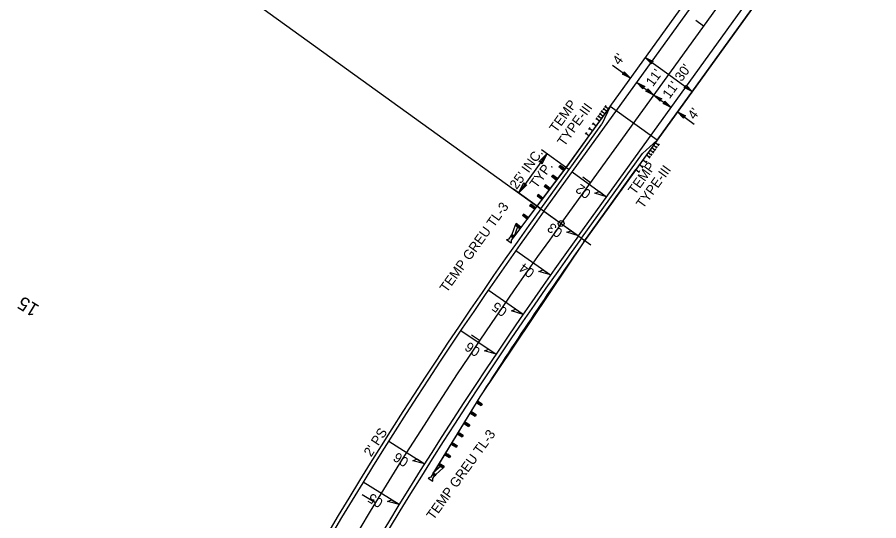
# Model space of a CAD drawing. Extents: x 2189637 to 2190858, y 386969 to 388736.
# Drawn here: x 2189954.9 to 2190401.4, y 387684.2 to 387945.3 of the extents above; entities that cross this region are included whole.
import ezdxf

# ---------------------------------------------------------------- set-up
doc = ezdxf.new("R2010")
doc.units = 0
for name, color, linetype in [('Exist Environmental Wetland Boundary Cogo Number', 7, 'Continuous'), ('Exist Environmental Wetland Boundary Cogo Point CELL', 7, 'Continuous'), ('Exist Horizontal Alignment Tick Label', 7, 'Continuous'), ('Exist Hydro Stream or Body of Water Leader', 7, 'Continuous'), ('Exist Hydro Swamp or Marsh', 7, 'Continuous'), ('Exist Property Corner CELL', 7, 'Continuous'), ('Exist Property Corner Cogo Elevation', 7, 'Continuous'), ('Exist Property Corner Cogo Number', 7, 'Continuous'), ('Exist Property Iron Pin Cogo Elevation', 7, 'Continuous'), ('Exist Property Iron Pin Text', 7, 'Continuous'), ('Exist Roads EOP', 7, 'Continuous'), ('Exist Roads EOT', 7, 'Continuous'), ('Exist Roads Soil', 7, 'Continuous'), ('Exist Structure Major Bridge Seam', 7, 'Continuous'), ('Exist Structure Minor Pipes RCP 18 Inch Cogo Comment', 7, 'Continuous'), ('Exist Structure Minor Pipes RCP 18 Inch Cogo Elevation', 7, 'Continuous'), ('Exist Structure Minor Pipes RCP 18 Inch Leader', 7, 'Continuous'), ('Prop Parcel Number Text', 7, 'Continuous')]:
    doc.layers.add(name, color=color, linetype=linetype)

msp = doc.modelspace()

# ---------------------------------------------------------------- linework, layer by layer
at = {"layer": 'Exist Environmental Wetland Boundary Cogo Number'}
for points in [[(2190262.12, 387899.07), (2190240.19, 387868.65), (2190212.09, 387831.29)], [(2190286.47, 387881.51), (2190248.49, 387828.75), (2190194.7, 387748.49), (2190170.3, 387708.6)]]:
    msp.add_lwpolyline(points, dxfattribs=at)
at = {"layer": 'Exist Environmental Wetland Boundary Cogo Point CELL'}
msp.add_line((2190236.81, 387838.31), (2190392.46, 388054.13), dxfattribs=at)
msp.add_arc((2192102.3, 386492.96), 2300, 144.20184, 152.59586, dxfattribs=at)
at = {"layer": 'Exist Horizontal Alignment Tick Label'}
for p, q in [((2190310.56, 387940.57), (2190306.51, 387943.5)), ((2190252.07, 387859.46), (2190248.01, 387862.39)), ((2190194.55, 387777.67), (2190190.4, 387780.46))]:
    msp.add_line(p, q, dxfattribs=at)
at = {"layer": 'Exist Hydro Stream or Body of Water Leader'}
msp.add_line((2190140.51, 387693.54), (2190133.69, 387697.71), dxfattribs=at)
at = {"layer": 'Exist Hydro Swamp or Marsh'}
for p, q in [((2190227.89, 387844.74), (2190383.54, 388060.57)), ((2190245.73, 387831.87), (2190401.38, 388047.7))]:
    msp.add_line(p, q, dxfattribs=at)
for radius in [2311, 2289]:
    msp.add_arc((2192102.3, 386492.96), radius, 144.20184, 152.59586, dxfattribs=at)
at = {"layer": 'Exist Property Corner CELL'}
for p, q in [((2190262.13, 387899.06), (2190363.91, 388040.19)), ((2190388.24, 388022.64), (2190286.52, 387881.47)), ((2190262.13, 387899.06), (2190257.9, 387889.78)), ((2190226.27, 387845.91), (2190257.9, 387889.78)), ((2190286.46, 387881.51), (2190278.99, 387874.57)), ((2190247.35, 387830.7), (2190278.99, 387874.57))]:
    msp.add_line(p, q, dxfattribs=at)
for radius, end in [(2313, 152.59586), (2287, 152.71824)]:
    msp.add_arc((2192102.3, 386492.96), radius, 144.20184, end, dxfattribs=at)
at = {"layer": 'Exist Property Corner Cogo Elevation'}
msp.add_line((2190063.73, 387963.13), (2190235.59, 387839.18), dxfattribs=at)
msp.add_circle((2190236.81, 387838.31), 1.5, dxfattribs=at)
at = {"layer": 'Exist Property Corner Cogo Number'}
for p, q in [((2190262.13, 387899.06), (2190363.91, 388040.19)), ((2190286.46, 387881.51), (2190388.24, 388022.64)), ((2190286.46, 387881.51), (2190262.13, 387899.06))]:
    msp.add_line(p, q, dxfattribs=at)
at = {"layer": 'Exist Property Iron Pin Cogo Elevation'}
for p, q in [((2190242.51, 387865.02), (2190260.36, 387852.15)), ((2190227.89, 387844.74), (2190245.73, 387831.87)), ((2190213.31, 387824.29), (2190231.29, 387811.62)), ((2190217.07, 387791.2), (2190198.95, 387803.68)), ((2190184.82, 387782.92), (2190203.07, 387770.64)), ((2190147.42, 387725.51), (2190166.03, 387713.77)), ((2190152.88, 387692.66), (2190134.14, 387704.19))]:
    msp.add_line(p, q, dxfattribs=at)
for points in [[(2190260.36, 387852.15), (2190254.32, 387854.04), (2190256.6, 387854.86)], [(2190245.73, 387831.87), (2190239.7, 387833.76), (2190241.98, 387834.58)], [(2190231.29, 387811.62), (2190225.23, 387813.44), (2190227.51, 387814.28)], [(2190217.07, 387791.2), (2190210.99, 387792.96), (2190213.26, 387793.83)], [(2190203.07, 387770.64), (2190196.98, 387772.33), (2190199.23, 387773.22)], [(2190166.03, 387713.77), (2190159.89, 387715.28), (2190162.12, 387716.24)], [(2190152.88, 387692.66), (2190146.72, 387694.1), (2190148.94, 387695.08)]]:
    msp.add_lwpolyline(points, close=True, dxfattribs=at)
at = {"layer": 'Exist Roads EOP'}
for p, q in [((2190280.39, 387924.38), (2190292.56, 387915.61)), ((2190263.35, 387920.44), (2190272.69, 387913.7)), ((2190292.56, 387915.61), (2190304.73, 387906.84)), ((2190275.94, 387911.36), (2190284.86, 387904.93)), ((2190284.86, 387904.93), (2190293.78, 387898.5)), ((2190297.03, 387896.17), (2190305.78, 387889.86)), ((2190240.89, 387866.19), (2190226.66, 387876.46)), ((2190229.43, 387874.46), (2190214.8, 387854.19)), ((2190226.27, 387845.91), (2190212.03, 387856.19))]:
    msp.add_line(p, q, dxfattribs=at)
at = {"layer": 'Exist Roads Soil'}
for points in [[(2190283.59, 387921.12), (2190280.39, 387924.38), (2190284.53, 387922.39), (2190283.6, 387922.07)], [(2190269.5, 387916.97), (2190272.69, 387913.7), (2190268.55, 387915.7), (2190269.49, 387916.02)], [(2190279.13, 387908.1), (2190275.94, 387911.36), (2190280.07, 387909.37), (2190279.14, 387909.06)], [(2190281.66, 387908.19), (2190284.86, 387904.93), (2190280.72, 387906.93), (2190281.66, 387907.24)], [(2190301.53, 387910.1), (2190304.73, 387906.84), (2190300.59, 387908.84), (2190301.53, 387909.15)], [(2190288.06, 387901.67), (2190284.86, 387904.93), (2190289, 387902.94), (2190288.06, 387902.62)], [(2190290.59, 387901.76), (2190293.78, 387898.5), (2190289.65, 387900.5), (2190290.58, 387900.81)], [(2190300.23, 387892.91), (2190297.03, 387896.17), (2190301.17, 387894.17), (2190300.24, 387893.86)], [(2190225.19, 387870.31), (2190229.43, 387874.46), (2190226.83, 387869.08), (2190226.43, 387870.3)], [(2190219.04, 387858.35), (2190214.8, 387854.19), (2190217.4, 387859.57), (2190217.8, 387858.36)]]:
    msp.add_lwpolyline(points, close=True, dxfattribs=at)
at = {"layer": 'Exist Structure Major Bridge Seam'}
for p, q in [((2190240.19, 387868.64), (2190212.1, 387831.28)), ((2190236.27, 387868.41), (2190235.67, 387867.62)), ((2190238.07, 387865.81), (2190235.67, 387867.62)), ((2190235.67, 387867.62), (2190237.47, 387867.51)), ((2190238.67, 387866.61), (2190236.27, 387868.41)), ((2190236.87, 387866.71), (2190236.27, 387868.41)), ((2190237.47, 387867.51), (2190236.87, 387866.71)), ((2190238.07, 387865.81), (2190236.87, 387866.71)), ((2190236.87, 387866.71), (2190238.67, 387866.61)), ((2190237.47, 387867.51), (2190238.07, 387865.81)), ((2190238.67, 387866.61), (2190238.07, 387865.81)), ((2190232.44, 387863.41), (2190231.84, 387862.61)), ((2190234.28, 387860.78), (2190231.84, 387862.61)), ((2190231.84, 387862.61), (2190233.66, 387862.49)), ((2190234.88, 387861.58), (2190232.44, 387863.41)), ((2190233.06, 387861.69), (2190232.44, 387863.41)), ((2190233.66, 387862.49), (2190233.06, 387861.69)), ((2190233.66, 387862.49), (2190234.28, 387860.78)), ((2190228.66, 387858.37), (2190228.06, 387857.57)), ((2190230.49, 387855.74), (2190228.06, 387857.57)), ((2190228.06, 387857.57), (2190229.87, 387857.46)), ((2190231.09, 387856.54), (2190228.66, 387858.37)), ((2190229.27, 387856.66), (2190228.66, 387858.37)), ((2190229.87, 387857.46), (2190229.27, 387856.66)), ((2190229.87, 387857.46), (2190230.49, 387855.74)), ((2190234.88, 387861.58), (2190233.06, 387861.69)), ((2190224.88, 387853.33), (2190224.28, 387852.53)), ((2190227.31, 387851.5), (2190224.88, 387853.33)), ((2190225.49, 387851.62), (2190224.88, 387853.33)), ((2190231.09, 387856.54), (2190229.27, 387856.66)), ((2190221.01, 387848.35), (2190220.41, 387847.55)), ((2190223.52, 387846.47), (2190221.01, 387848.35)), ((2190221.66, 387846.61), (2190221.01, 387848.35)), ((2190226.7, 387850.7), (2190224.28, 387852.53)), ((2190224.28, 387852.53), (2190226.09, 387852.42)), ((2190226.09, 387852.42), (2190225.49, 387851.62)), ((2190227.31, 387851.5), (2190225.49, 387851.62)), ((2190226.09, 387852.42), (2190226.7, 387850.7)), ((2190227.31, 387851.5), (2190226.7, 387850.7)), ((2190222.92, 387845.67), (2190220.41, 387847.55)), ((2190220.41, 387847.55), (2190222.26, 387847.41)), ((2190222.26, 387847.41), (2190221.66, 387846.61)), ((2190223.52, 387846.47), (2190221.66, 387846.61)), ((2190222.26, 387847.41), (2190222.92, 387845.67)), ((2190217.33, 387843.23), (2190216.73, 387842.43)), ((2190219.13, 387840.63), (2190216.73, 387842.43)), ((2190216.73, 387842.43), (2190218.53, 387842.33)), ((2190219.73, 387841.43), (2190217.33, 387843.23)), ((2190217.93, 387841.53), (2190217.33, 387843.23)), ((2190218.53, 387842.33), (2190217.93, 387841.53)), ((2190219.73, 387841.43), (2190217.93, 387841.53)), ((2190218.53, 387842.33), (2190219.13, 387840.63)), ((2190212.89, 387837.44), (2190211.2, 387832.58)), ((2190214.12, 387836.52), (2190212.4, 387831.68)), ((2190213.49, 387838.24), (2190212.89, 387837.44)), ((2190215.34, 387835.6), (2190212.89, 387837.44)), ((2190212.89, 387837.44), (2190214.72, 387837.32)), ((2190215.94, 387836.4), (2190213.49, 387838.24)), ((2190214.12, 387836.52), (2190213.49, 387838.24)), ((2190214.72, 387837.32), (2190214.12, 387836.52)), ((2190215.94, 387836.4), (2190214.12, 387836.52)), ((2190214.72, 387837.32), (2190215.34, 387835.6)), ((2190209.83, 387830.36), (2190211.03, 387832.02)), ((2190211.2, 387832.58), (2190210.6, 387831.78)), ((2190211.8, 387830.88), (2190210.6, 387831.78)), ((2190210.6, 387831.78), (2190212.4, 387831.68)), ((2190212.02, 387831.3), (2190210.82, 387829.64)), ((2190211.2, 387832.58), (2190210.9, 387832.18)), ((2190211.03, 387832.02), (2190211.52, 387831.66)), ((2190212.4, 387831.68), (2190211.2, 387832.58)), ((2190211.8, 387830.88), (2190211.2, 387832.58)), ((2190211.52, 387831.66), (2190212.02, 387831.3)), ((2190208.44, 387829.91), (2190209.83, 387830.36)), ((2190210.82, 387828.18), (2190208.44, 387829.91)), ((2190210.82, 387829.64), (2190210.82, 387828.18)), ((2190194.69, 387748.49), (2190170.29, 387708.61)), ((2190193.36, 387746.32), (2190192.84, 387745.47)), ((2190193.36, 387746.32), (2190195.92, 387744.76)), ((2190194.12, 387744.69), (2190193.36, 387746.32)), ((2190194.64, 387745.54), (2190192.84, 387745.47)), ((2190192.84, 387745.47), (2190195.4, 387743.9)), ((2190192.84, 387745.47), (2190194.12, 387744.69)), ((2190194.64, 387745.54), (2190194.12, 387744.69)), ((2190194.12, 387744.69), (2190195.92, 387744.76)), ((2190195.4, 387743.9), (2190194.64, 387745.54)), ((2190195.92, 387744.76), (2190195.4, 387743.9)), ((2190191.37, 387740.15), (2190189.55, 387740.09)), ((2190189.55, 387740.09), (2190192.15, 387738.5)), ((2190190.07, 387740.95), (2190192.68, 387739.35)), ((2190190.07, 387740.95), (2190190.85, 387739.3)), ((2190191.37, 387740.15), (2190190.85, 387739.3)), ((2190190.85, 387739.3), (2190192.68, 387739.35)), ((2190192.15, 387738.5), (2190191.37, 387740.15)), ((2190192.68, 387739.35), (2190192.15, 387738.5)), ((2190188.08, 387734.78), (2190186.26, 387734.72)), ((2190186.26, 387734.72), (2190188.86, 387733.13)), ((2190186.78, 387735.57), (2190189.38, 387733.98)), ((2190186.78, 387735.57), (2190187.56, 387733.92)), ((2190188.08, 387734.78), (2190187.56, 387733.92)), ((2190187.56, 387733.92), (2190189.38, 387733.98)), ((2190188.86, 387733.13), (2190188.08, 387734.78)), ((2190189.38, 387733.98), (2190188.86, 387733.13)), ((2190183.5, 387730.2), (2190182.98, 387729.34)), ((2190184.79, 387729.4), (2190182.98, 387729.34)), ((2190182.98, 387729.34), (2190185.56, 387727.76)), ((2190183.5, 387730.2), (2190186.09, 387728.61)), ((2190183.5, 387730.2), (2190184.27, 387728.55)), ((2190184.79, 387729.4), (2190184.27, 387728.55)), ((2190184.27, 387728.55), (2190186.09, 387728.61)), ((2190185.56, 387727.76), (2190184.79, 387729.4)), ((2190186.09, 387728.61), (2190185.56, 387727.76)), ((2190181.55, 387724), (2190179.69, 387723.97)), ((2190179.69, 387723.97), (2190182.36, 387722.33)), ((2190180.21, 387724.82), (2190182.89, 387723.18)), ((2190180.21, 387724.82), (2190181.03, 387723.15)), ((2190181.55, 387724), (2190181.03, 387723.15)), ((2190182.36, 387722.33), (2190181.55, 387724)), ((2190176.92, 387719.44), (2190179.48, 387717.88)), ((2190176.92, 387719.44), (2190177.68, 387717.81)), ((2190181.03, 387723.15), (2190182.89, 387723.18)), ((2190182.89, 387723.18), (2190182.36, 387722.33)), ((2190178.2, 387718.66), (2190176.4, 387718.59)), ((2190176.4, 387718.59), (2190178.96, 387717.03)), ((2190178.2, 387718.66), (2190177.68, 387717.81)), ((2190177.68, 387717.81), (2190179.48, 387717.88)), ((2190178.96, 387717.03), (2190178.2, 387718.66)), ((2190179.48, 387717.88), (2190178.96, 387717.03)), ((2190174.42, 387712.42), (2190170.55, 387709.03)), ((2190175.73, 387711.62), (2190171.83, 387708.25)), ((2190174.94, 387713.27), (2190173.11, 387713.22)), ((2190173.11, 387713.22), (2190175.73, 387711.62)), ((2190173.63, 387714.07), (2190176.25, 387712.47)), ((2190173.63, 387714.07), (2190174.42, 387712.42)), ((2190174.94, 387713.27), (2190174.42, 387712.42)), ((2190174.42, 387712.42), (2190176.25, 387712.47)), ((2190175.73, 387711.62), (2190174.94, 387713.27)), ((2190176.25, 387712.47), (2190175.73, 387711.62)), ((2190169.24, 387706.81), (2190167.88, 387706.29)), ((2190167.88, 387706.29), (2190170.36, 387704.71)), ((2190170.34, 387708.54), (2190169.24, 387706.81)), ((2190170.03, 387708.18), (2190171.83, 387708.25)), ((2190170.03, 387708.18), (2190171.31, 387707.4)), ((2190170.27, 387706.16), (2190171.37, 387707.89)), ((2190170.36, 387704.71), (2190170.27, 387706.16)), ((2190170.86, 387708.21), (2190170.34, 387708.54)), ((2190170.55, 387709.03), (2190171.83, 387708.25)), ((2190171.31, 387707.4), (2190170.55, 387709.03)), ((2190171.37, 387707.89), (2190170.86, 387708.21)), ((2190171.83, 387708.25), (2190171.31, 387707.4)), ((2190171.83, 387708.25), (2190171.57, 387707.83))]:
    msp.add_line(p, q, dxfattribs=at)
at = {"layer": 'Exist Structure Minor Pipes RCP 18 Inch Cogo Comment'}
for p, q in [((2190251.16, 387883.85), (2190240.19, 387868.64)), ((2190248.48, 387828.76), (2190275.5, 387866.3))]:
    msp.add_line(p, q, dxfattribs=at)
msp.add_arc((2192118.58, 386517.2), 2284.17, 144.95676, 147.38071, dxfattribs=at)
at = {"layer": 'Exist Structure Minor Pipes RCP 18 Inch Cogo Elevation'}
for p, q in [((2190262.13, 387899.06), (2190251.16, 387883.85)), ((2190259.01, 387898.16), (2190258.34, 387897.23)), ((2190260.3, 387896.52), (2190258.68, 387897.69)), ((2190259.93, 387899.43), (2190259.26, 387898.5)), ((2190261.22, 387897.79), (2190259.59, 387898.96)), ((2190255.36, 387893.09), (2190254.69, 387892.16)), ((2190256.27, 387894.36), (2190255.6, 387893.43)), ((2190257.56, 387892.72), (2190255.94, 387893.89)), ((2190257.19, 387895.62), (2190256.52, 387894.7)), ((2190258.47, 387893.99), (2190256.85, 387895.16)), ((2190258.1, 387896.89), (2190257.43, 387895.96)), ((2190259.39, 387895.26), (2190257.77, 387896.43)), ((2190253.53, 387890.56), (2190252.86, 387889.63)), ((2190254.82, 387888.92), (2190253.2, 387890.09)), ((2190256.65, 387891.46), (2190255.02, 387892.63)), ((2190249.88, 387885.49), (2190249.21, 387884.56)), ((2190251.16, 387883.85), (2190249.54, 387885.02)), ((2190251.7, 387888.02), (2190251.03, 387887.09)), ((2190252.99, 387886.39), (2190251.37, 387887.56)), ((2190286.46, 387881.51), (2190275.5, 387866.3)), ((2190285.55, 387880.24), (2190287.17, 387879.07)), ((2190281.9, 387875.17), (2190283.52, 387874)), ((2190282.81, 387876.44), (2190284.43, 387875.27)), ((2190283.72, 387877.71), (2190285.34, 387876.54)), ((2190284.77, 387875.74), (2190284.1, 387874.81)), ((2190284.64, 387878.98), (2190286.26, 387877.81)), ((2190285.68, 387877), (2190285.01, 387876.07)), ((2190286.59, 387878.27), (2190285.92, 387877.34)), ((2190287.51, 387879.54), (2190286.84, 387878.61)), ((2190279.16, 387871.37), (2190280.78, 387870.2)), ((2190281.11, 387870.67), (2190280.44, 387869.74)), ((2190280.98, 387873.91), (2190282.6, 387872.74)), ((2190282.94, 387873.2), (2190282.27, 387872.27)), ((2190283.85, 387874.47), (2190283.18, 387873.54)), ((2190275.5, 387866.3), (2190277.12, 387865.13)), ((2190277.33, 387868.83), (2190278.95, 387867.67)), ((2190279.29, 387868.13), (2190278.62, 387867.2)), ((2190277.46, 387865.59), (2190276.79, 387864.66))]:
    msp.add_line(p, q, dxfattribs=at)
at = {"layer": 'Exist Structure Minor Pipes RCP 18 Inch Leader'}
msp.add_line((2190232.73, 387841.23), (2190252.21, 387827.2), dxfattribs=at)

# ---------------------------------------------------------------- texts
at = {"layer": 'Exist Property Iron Pin Text'}
msp.add_text('15', height=7, rotation=148.5343, dxfattribs=at).set_placement((2189966.8, 387795.46))
at = {"layer": 'Exist Roads EOT'}
for s, rotation, p in [("4'", 54.2018, (2190267.04, 387920.11)), ("30'", 54.2018, (2190299.28, 387911.59)), ("11'", 54.2018, (2190284.34, 387908.97)), ("11'", 54.2018, (2190292.94, 387902.63)), ("4'", 54.2018, (2190305.95, 387891.85)), ("25' INC.", 54.2018, (2190213.72, 387855.62)), ('TYP.', 54.2018, (2190224.1, 387856.14)), ("2' PS", 56.9457, (2190138.3, 387716.99))]:
    msp.add_text(s, height=5, rotation=rotation, dxfattribs=at).set_placement(p)
at = {"layer": 'Exist Structure Major Bridge Seam'}
for s, p in [('TEMP', (2190234.31, 387885.06)), ('TYPE-III', (2190238.43, 387877.95)), ('TEMP', (2190275.11, 387852.84)), ('TYPE-III', (2190279.23, 387845.73)), ('TEMP GREU TL-3', (2190177.5, 387802.17)), ('TEMP GREU TL-3', (2190170.65, 387684.23))]:
    msp.add_text(s, height=5, rotation=54.2018, dxfattribs=at).set_placement(p)
at = {"layer": 'Prop Parcel Number Text'}
for s, rotation, p in [('02', 144.227, (2190252.68, 387854.77)), ('03', 144.227, (2190237.98, 387834.59)), ('04', 144.227, (2190223.45, 387813.78)), ('05', 145.4725, (2190209.27, 387793.75)), ('06', 146.0953, (2190195.31, 387773.05)), ('06', 147.794, (2190158.2, 387715.96)), ('05', 148.4167, (2190144.95, 387694.8))]:
    msp.add_text(s, height=5, rotation=rotation, dxfattribs=at).set_placement(p)

doc.saveas('drawing.dxf')
